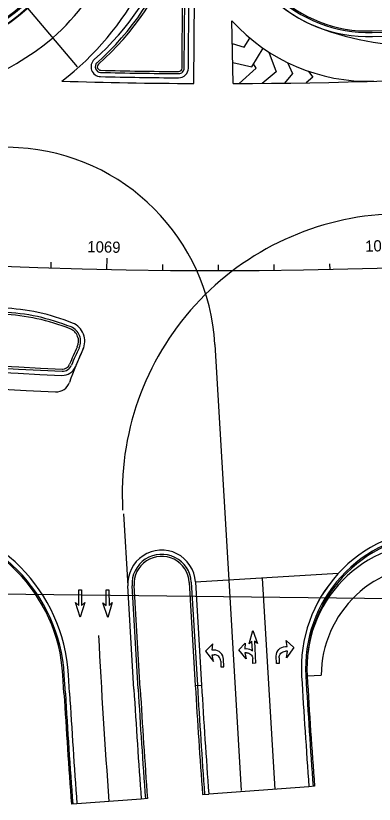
# Model space of a CAD drawing. Extents: x 468143 to 491361, y 1438528 to 1468730.
# Drawn here: x 489072.4 to 489200.9, y 1466490.6 to 1466773.1 of the extents above; entities that cross this region are included whole.
import ezdxf

# ---------------------------------------------------------------- set-up
doc = ezdxf.new("R2010")
doc.units = 0
doc.layers.add('Default', color=7, linetype='Continuous')
doc.layers.add('Xreference_dp', color=7, linetype='Continuous')

# ---------------------------------------------------------------- blocks, each defined once
blk = doc.blocks.new('DARightThru')
at = {"layer": 'Default'}
for points in [[(5.05, 2.17), (8.83, 2.17), (7.83, 1), (13.08, 2.67), (7.83, 4.33), (8.83, 3.17), (0, 3.17), (0, 2.17), (2, 2.17)], [(4.33, -0.83), (2, -0.5), (5.67, -3.17), (8.25, -0.5), (6, -0.83), (6, -0.17)], [(4.33, -0.17), (4.33, -0.83)]]:
    blk.add_lwpolyline(points, dxfattribs=at)
for centre, radius, start, end in [((2, -0.17), 2.33, 360, 90), ((2.67, -0.17), 3.33, 0, 44.427)]:
    blk.add_arc(centre, radius, start, end, dxfattribs=at)
blk = doc.blocks.new('DALeftTurn_1')
at = {"layer": 'Default'}
for points in [[(5.67, 3.17), (2, 0.5), (4.33, 0.83), (4.33, 0.17)], [(6, 0.17), (6, 0.83), (8.25, 0.5), (5.67, 3.17)], [(2, -2.17), (0, -2.17), (0, -3.17), (2.67, -3.17)]]:
    blk.add_lwpolyline(points, dxfattribs=at)
for centre, radius in [((2, 0.17), 2.33), ((2.67, 0.17), 3.33)]:
    blk.add_arc(centre, radius, 270, 0, dxfattribs=at)
blk = doc.blocks.new('DAMerge_2')
at = {"layer": 'Default'}
blk.add_lwpolyline([(0.71, -4.09), (0, -3.39), (3.95, 0.56), (2.42, 0.68), (7.31, 3.21), (4.77, -1.68), (4.66, -0.15), (0.71, -4.09)], dxfattribs=at)
blk = doc.blocks.new('DAMerge_6')
at = {"layer": 'Default'}
blk.add_lwpolyline([(0.71, -4.09), (0, -3.39), (3.95, 0.56), (2.42, 0.68), (7.31, 3.21), (4.77, -1.68), (4.66, -0.15), (0.71, -4.09)], dxfattribs=at)

msp = doc.modelspace()

# ---------------------------------------------------------------- linework, layer by layer
at = {"layer": 'Xreference_dp'}
for p, q in [((489132.05, 1466754.38), (489132.36, 1466796.34)), ((489132.8, 1466754.38), (489133.11, 1466796.34)), ((489134.3, 1466754.36), (489134.61, 1466796.32)), ((489136.26, 1466748.86), (489136.6, 1466795.13)), ((489076.61, 1466775.84), (489094.44, 1466754.77)), ((489150.37, 1466748.84), (489149.83, 1466771.35)), ((489158.55, 1466754.28), (489152.51, 1466748.85)), ((489158.55, 1466754.28), (489157.67, 1466755.86)), ((489073.36, 1466725.83), (489027.84, 1466728.51)), ((489105.09, 1466682.25), (489105.17, 1466686.25)), ((489085.09, 1466682.78), (489085.16, 1466684.77)), ((489125.08, 1466681.94), (489125.1, 1466683.94)), ((489145.08, 1466681.83), (489145.08, 1466683.83)), ((489165.08, 1466681.94), (489165.06, 1466683.94)), ((489185.08, 1466682.25), (489185.04, 1466684.25)), ((489143.82, 1466655.38), (489148.81, 1466570.94)), ((489111.06, 1466594.64), (489112.59, 1466568.8)), ((489188.01, 1466573.25), (489136.83, 1466570.23)), ((489134.58, 1466570.1), (489136.76, 1466533.18)), ((489135.33, 1466570.14), (489137.51, 1466533.23)), ((489136.83, 1466570.23), (489139.01, 1466533.32)), ((489136.83, 1466570.23), (489139.01, 1466533.32)), ((489148.81, 1466570.94), (489153.26, 1466495.49)), ((489160.79, 1466571.65), (489165.26, 1466495.9)), ((489114.77, 1466531.89), (489112.59, 1466568.8)), ((489114.77, 1466531.89), (489112.59, 1466568.8)), ((489116.27, 1466531.97), (489114.09, 1466568.89)), ((489117.02, 1466532.02), (489114.84, 1466568.93)), ((488998.14, 1466566.74), (489254.9, 1466563.72)), ((489089.7, 1466530.4), (489089.32, 1466536.83)), ((489090.2, 1466530.43), (489089.82, 1466536.86)), ((489091.7, 1466530.52), (489091.32, 1466536.95)), ((489091.7, 1466530.52), (489091.32, 1466536.95)), ((489176.88, 1466536.57), (489181.87, 1466536.86)), ((489136.76, 1466533.18), (489139.01, 1466533.32)), ((489177.5, 1466496.88), (489141.6, 1466494.24)), ((489179.5, 1466497.03), (489177.5, 1466496.88)), ((489139.36, 1466494.07), (489141.6, 1466494.24)), ((489117.39, 1466492.45), (489094.34, 1466490.75)), ((489119.63, 1466492.62), (489117.39, 1466492.45)), ((489094.34, 1466490.75), (489092.34, 1466490.61))]:
    msp.add_line(p, q, dxfattribs=at)
for points in [[(489150.02, 1466763.21), (489154.23, 1466761.81), (489156.27, 1466765.14)], [(489150.19, 1466756.42), (489157.07, 1466754.86), (489161.06, 1466761.47)], [(489163.09, 1466760.11), (489165.73, 1466753.02), (489160.74, 1466748.9)], [(489169.78, 1466756.35), (489171.63, 1466752.43), (489168.73, 1466748.99)], [(489177.4, 1466753.2), (489178.94, 1466751.12), (489176.54, 1466749.1)]]:
    msp.add_lwpolyline(points, dxfattribs=at)
for centre, radius, start, end in [((489145.02, 1468591.69), 1909.86, 245.36712, 306.9274), ((489145.02, 1468591.69), 1824.86, 271.73266, 299.99002), ((489145.02, 1468591.69), 1825.36, 271.73266, 299.99002), ((489145.02, 1468591.69), 1826.86, 271.73266, 299.99002), ((489026.46, 1466831.82), 75, 266.1456, 356.905), ((489026.46, 1466831.82), 73.5, 266.1456, 356.905), ((489026.46, 1466831.82), 73, 266.1456, 356.905), ((489025.96, 1466831.83), 75.5, 296.9428, 356.905), ((489025.96, 1466831.83), 89.5, 311.8401, 356.905), ((489025.96, 1466831.83), 103.5, 307.4753, 356.905), ((489198.75, 1466815.65), 50, 179.5833, 271.7327), ((489198.75, 1466815.65), 50, 179.5833, 248.9768), ((489198.75, 1466815.65), 48.5, 179.5833, 271.7327), ((489198.75, 1466815.65), 48, 179.5833, 271.7327), ((489145.02, 1468591.69), 1842.86, 270.16616, 283.80836), ((489033.94, 1466832.01), 100, 311.7706, 339.8462), ((489033.94, 1466832.01), 101.5, 311.7706, 339.8462), ((489033.94, 1466832.01), 102.25, 311.7706, 339.8462), ((489167.8, 1468440.54), 1804, 246.0273, 267.4233), ((489198.75, 1466815.65), 66, 222.1615, 271.7327), ((489216.69, 1466862.32), 100, 248.9768, 272.3729), ((489018.22, 1466847.38), 106.35, 275.363, 309.3569), ((489102.89, 1466754.82), 3.5, 131.7706, 268.686), ((489102.89, 1466754.82), 2, 131.7706, 268.686), ((489102.89, 1466754.82), 1.25, 131.7706, 268.686), ((489130.8, 1466754.39), 3.5, 269.5565, 359.5833), ((489130.8, 1466754.39), 1.25, 269.5565, 359.5833), ((489130.8, 1466754.39), 2, 269.5565, 359.5833), ((489145.02, 1468591.69), 1840.86, 268.68601, 269.55649), ((489145.02, 1468591.69), 1839.36, 268.68601, 269.55649), ((489145.02, 1468591.69), 1838.61, 268.68601, 269.55649), ((489145.02, 1468591.69), 1842.86, 268.25565, 269.72757), ((489167.8, 1468440.54), 1796.5, 251.49066, 267.48938), ((489167.8, 1468440.54), 1795.75, 251.49066, 267.4904), ((489167.8, 1468440.54), 1798, 251.49066, 267.48619), ((489068.95, 1466650.96), 75, 3.3796, 86.6289), ((489210.81, 1466601.92), 100.25, 91.8935, 183.3796), ((489064.73, 1466593.45), 72.75, 68.0321, 87.6989), ((489064.73, 1466593.45), 73.5, 68.0321, 87.6989), ((489064.73, 1466593.45), 75, 68.0321, 87.6989), ((489064.73, 1466593.45), 75, 68.0321, 87.6989), ((489090.17, 1466656.51), 4.75, 334.6217, 68.0321), ((489090.17, 1466656.51), 5.5, 334.6217, 68.0321), ((489090.17, 1466656.51), 7, 334.6217, 68.0321), ((489090.17, 1466656.51), 7, 334.6217, 68.0321), ((489204.91, 1466602.08), 120, 154.6217, 160.7159), ((489204.91, 1466602.08), 122.25, 154.672, 157.8208), ((489204.91, 1466602.08), 121.5, 154.672, 157.8208), ((489204.91, 1466602.08), 120, 154.6217, 157.8208), ((489089.16, 1466649.27), 5, 267.4862, 337.8208), ((489089.16, 1466649.27), 3.5, 267.4862, 337.8208), ((489089.16, 1466649.27), 2.75, 267.4862, 337.8208), ((489086.93, 1466643.36), 5, 267.4233, 340.7159), ((489031.42, 1466533.41), 60, 3.3796, 85.9097), ((489031.42, 1466533.41), 60, 3.3796, 85.9097), ((489031.42, 1466533.41), 58, 3.3796, 85.9097), ((489031.42, 1466533.41), 58.5, 3.3796, 85.9097), ((489224.8, 1466539.4), 50, 91.7172, 183.3573), ((489224.8, 1466539.4), 50, 91.7172, 183.3796), ((489224.8, 1466539.4), 48.5, 91.7172, 183.3573), ((489224.8, 1466539.4), 48, 91.7172, 183.3573), ((489221.79, 1466539.41), 45, 87.8888, 183.6184), ((489124.71, 1466569.52), 12.14, 3.3796, 183.3796), ((489124.71, 1466569.52), 12.14, 3.3796, 183.3796), ((489124.71, 1466569.52), 10.64, 3.3796, 183.3796), ((489124.71, 1466569.52), 9.89, 3.3796, 183.3796), ((489221.87, 1466536.42), 40, 87.3937, 179.3692), ((491823.33, 1466691.83), 2724.89, 182.96081, 184.2141), ((491823.33, 1466691.83), 2653, 183.35733, 184.2141), ((491823.33, 1466691.83), 2653, 183.35733, 184.2141), ((491823.33, 1466691.83), 2651.5, 183.35733, 184.2141), ((491823.33, 1466691.83), 2651, 183.35733, 184.2141), ((491823.33, 1466691.83), 2689, 183.37959, 184.2141), ((491823.33, 1466691.83), 2689, 183.37959, 184.2141), ((491823.33, 1466691.83), 2737.89, 183.37959, 184.2141), ((491823.33, 1466691.83), 2736.39, 183.37959, 184.2141), ((491823.33, 1466691.83), 2736.39, 183.37959, 184.2141), ((491823.33, 1466691.83), 2713.28, 183.37959, 184.2141), ((491823.33, 1466691.83), 2713.28, 183.37959, 184.2141), ((491823.33, 1466691.83), 2711.78, 183.37959, 184.2141), ((491823.33, 1466691.83), 2711.03, 183.37959, 184.2141), ((491823.33, 1466691.83), 2691.25, 183.37959, 184.2141), ((491823.33, 1466691.83), 2690.5, 183.37959, 184.2141), ((491823.33, 1466691.83), 2738.39, 183.37959, 184.2141)]:
    msp.add_arc(centre, radius, start, end, dxfattribs=at)

# ---------------------------------------------------------------- block references
for name, p, rotation in [('DAMerge_2', (489098.38, 1466565.02), -135.1364510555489), ('DAMerge_6', (489098.38, 1466565.02), -135.1364510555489), ('DAMerge_2', (489108.2, 1466565.05), -134.1773077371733), ('DAMerge_6', (489108.2, 1466565.05), -134.1773077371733), ('DALeftTurn_1', (489143.79, 1466539.81), 91.52883288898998)]:
    msp.add_blockref(name, p, dxfattribs=dict(at, rotation=rotation))
at = {"layer": 'Xreference_dp', "xscale": 0.9000000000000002, "yscale": -0.9, "rotation": 92.65839847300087}
msp.add_blockref('DARightThru', (489155.49, 1466540.96), dxfattribs=at)
at = {"layer": 'Xreference_dp', "yscale": -1, "rotation": 90.90828250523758}
msp.add_blockref('DALeftTurn_1', (489169.01, 1466541.07), dxfattribs=at)

# ---------------------------------------------------------------- texts
at = {"layer": 'Xreference_dp'}
for s, rotation, p in [('1069', 358.8017, (489098.03, 1466688.4)), ('1070', 1.8018, (489197.71, 1466688.55))]:
    msp.add_text(s, height=4, rotation=rotation, dxfattribs=at).set_placement(p)

doc.saveas('drawing.dxf')
